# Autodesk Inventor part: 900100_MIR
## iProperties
Created: 2007-12
Part Number: 900100_MIR
Material: Acetal Resin, Black
Description: 1200 POWER SEAT SWITCH CONTROL
Document SubType Name: Modeling
Designer: jjohnson
Mass: 54.0389 g
Surface Area: 125.096 cm^2
Volume: 37.922 cm^3
Density: 1.425 g/cm^3
Component Category: Electrical
Author: EP
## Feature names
1. TaggingFeature2
